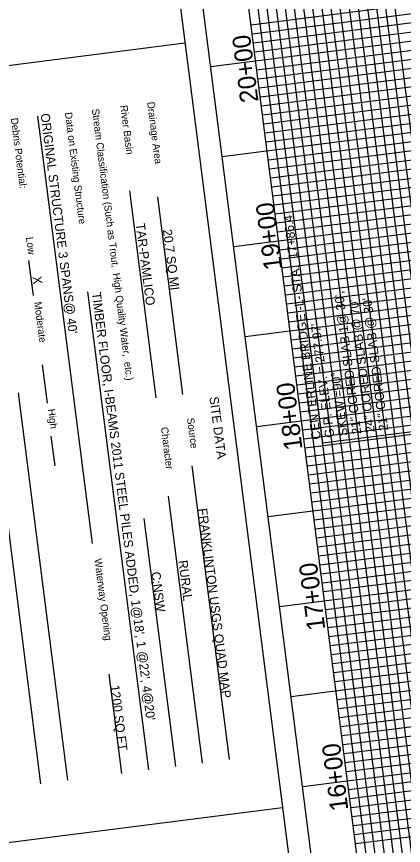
# Model space of a CAD drawing. Extents: x 2166991 to 2168450, y 842134 to 844444.
# Drawn here: x 2167499 to 2167712.5, y 843150.2 to 843607.1 of the extents above; entities that cross this region are included whole.
import ezdxf

# ---------------------------------------------------------------- set-up
doc = ezdxf.new("R2010")
doc.units = 0
for name, color, linetype in [('Exist Hydrographic Top of Bank', 7, 'Continuous'), ('Exist Plan Preparation Drainage Notes Label', 7, 'Continuous'), ('Prop Erosion Embankment Toe Protection Label', 7, 'Continuous'), ('Prop Erosion Embankment Toe Protection with Rip Rap 3 Detail CELL', 7, 'Continuous')]:
    doc.layers.add(name, color=color, linetype=linetype)

msp = doc.modelspace()

# ---------------------------------------------------------------- linework, layer by layer
at = {"layer": 'Exist Hydrographic Top of Bank'}
for p, q in [((2167668.02, 843371.86), (2167649.73, 843515.1)), ((2167765.56, 843384.32), (2167668.02, 843371.86))]:
    msp.add_line(p, q, dxfattribs=at)
at = {"layer": 'Exist Plan Preparation Drainage Notes Label'}
for p, q in [((2167538.09, 844014.21), (2167699.63, 842749.49)), ((2167538.09, 844014.21), (2167699.63, 842749.49)), ((2167785.16, 842770.49), (2167626.78, 844010.42)), ((2167710.76, 842760.99), (2167552.39, 844000.92)), ((2167735.56, 842764.16), (2167577.19, 844004.08)), ((2167796.87, 842797.19), (2167644.83, 843987.52)), ((2167801.83, 842797.82), (2167649.79, 843988.15)), ((2167806.79, 842798.46), (2167654.75, 843988.79)), ((2167811.75, 842799.09), (2167659.71, 843989.42)), ((2167757.19, 842792.12), (2167605.15, 843982.45)), ((2167762.15, 842792.76), (2167610.11, 843983.09)), ((2167767.11, 842793.39), (2167615.07, 843983.72)), ((2167772.07, 842794.02), (2167620.03, 843984.35)), ((2167777.03, 842794.66), (2167624.99, 843984.99)), ((2167786.95, 842795.92), (2167634.91, 843986.25)), ((2167791.91, 842796.56), (2167639.87, 843986.89)), ((2167737.35, 842789.59), (2167585.31, 843979.92)), ((2167742.31, 842790.22), (2167590.27, 843980.55)), ((2167747.27, 842790.86), (2167595.23, 843981.18)), ((2167752.23, 842791.49), (2167600.19, 843981.82)), ((2168124.47, 843665.7), (2167628.5, 843602.35)), ((2168125.1, 843660.74), (2167629.13, 843597.39)), ((2168125.74, 843655.78), (2167629.77, 843592.43)), ((2168126.37, 843650.82), (2167630.4, 843587.47)), ((2168127.01, 843645.86), (2167606.24, 843579.34)), ((2168127.64, 843640.9), (2167631.67, 843577.55)), ((2168128.27, 843635.94), (2167632.3, 843572.59)), ((2168128.91, 843630.98), (2167632.94, 843567.63)), ((2168129.54, 843626.02), (2167633.57, 843562.67)), ((2168130.17, 843621.06), (2167634.2, 843557.71)), ((2168130.81, 843616.1), (2167634.84, 843552.75)), ((2168131.44, 843611.14), (2167635.47, 843547.79)), ((2168132.07, 843606.18), (2167636.1, 843542.83)), ((2168132.71, 843601.22), (2167636.74, 843537.87)), ((2168133.34, 843596.26), (2167612.57, 843529.74)), ((2167046.37, 843522.95), (2167591.94, 843592.64)), ((2168133.97, 843591.3), (2167638, 843527.95)), ((2168134.61, 843586.34), (2167638.64, 843522.99)), ((2168135.24, 843581.38), (2167639.27, 843518.03)), ((2168135.87, 843576.42), (2167639.9, 843513.07)), ((2168136.51, 843571.46), (2167640.54, 843508.11)), ((2168137.14, 843566.5), (2167641.17, 843503.15)), ((2168137.77, 843561.54), (2167641.8, 843498.19)), ((2168138.41, 843556.58), (2167642.44, 843493.23)), ((2167540.89, 843316.64), (2167510.79, 843552.29)), ((2168139.04, 843551.62), (2167643.07, 843488.27)), ((2167512.44, 843184.21), (2167466.16, 843546.59)), ((2168139.68, 843546.66), (2167618.91, 843480.15)), ((2168140.31, 843541.7), (2167644.34, 843478.35)), ((2168140.94, 843536.74), (2167644.97, 843473.39)), ((2168141.58, 843531.78), (2167645.61, 843468.43)), ((2168142.21, 843526.83), (2167646.24, 843463.47)), ((2168142.84, 843521.87), (2167646.87, 843458.52)), ((2168143.48, 843516.91), (2167647.51, 843453.56)), ((2168144.11, 843511.95), (2167648.14, 843448.6)), ((2167576.04, 843396.95), (2167561.47, 843511.05)), ((2167590.88, 843398.85), (2167576.97, 843507.77)), ((2168144.74, 843506.99), (2167648.77, 843443.64)), ((2168145.38, 843502.03), (2167649.41, 843438.68)), ((2168146.01, 843497.07), (2167625.24, 843430.55)), ((2168146.64, 843492.11), (2167650.67, 843428.76)), ((2168147.28, 843487.15), (2167651.31, 843423.8)), ((2168147.91, 843482.19), (2167651.94, 843418.84)), ((2168148.54, 843477.23), (2167652.57, 843413.88)), ((2167508.31, 843453.37), (2167505.85, 843472.59)), ((2168149.18, 843472.27), (2167653.21, 843408.92)), ((2168149.81, 843467.31), (2167653.84, 843403.96)), ((2168150.44, 843462.35), (2167654.47, 843399)), ((2168151.08, 843457.39), (2167655.11, 843394.04)), ((2167571.96, 843191.81), (2167538.29, 843455.42)), ((2168151.71, 843452.43), (2167655.74, 843389.08)), ((2168152.35, 843447.47), (2167631.58, 843380.95)), ((2168152.98, 843442.51), (2167657.01, 843379.16)), ((2168153.61, 843437.55), (2167657.64, 843374.2)), ((2168154.25, 843432.59), (2167658.28, 843369.24)), ((2168154.88, 843427.63), (2167658.91, 843364.28)), ((2168155.51, 843422.67), (2167659.54, 843359.32)), ((2168156.15, 843417.71), (2167660.18, 843354.36)), ((2167513.19, 843415.17), (2167515.89, 843393.99)), ((2168156.78, 843412.75), (2167660.81, 843349.4)), ((2168157.41, 843407.79), (2167661.44, 843344.44)), ((2168158.05, 843402.83), (2167662.08, 843339.48)), ((2167527.32, 843186.11), (2167500.04, 843399.72)), ((2168158.68, 843397.87), (2167637.91, 843331.35)), ((2168159.31, 843392.91), (2167663.34, 843329.56)), ((2168159.95, 843387.95), (2167663.98, 843324.6)), ((2168160.58, 843382.99), (2167664.61, 843319.64)), ((2167520.3, 843359.51), (2167518.21, 843375.87)), ((2168161.21, 843378.03), (2167665.24, 843314.68)), ((2168161.85, 843373.07), (2167665.88, 843309.72)), ((2168162.48, 843368.11), (2167666.51, 843304.76)), ((2168163.11, 843363.15), (2167667.14, 843299.8)), ((2167616.62, 843197.52), (2167595.94, 843359.41)), ((2168163.75, 843358.2), (2167667.78, 843294.84)), ((2168164.38, 843353.24), (2167668.41, 843289.89)), ((2168165.02, 843348.28), (2167644.25, 843281.76)), ((2168165.65, 843343.32), (2167669.68, 843279.97)), ((2167601.72, 843195.61), (2167582.94, 843342.63)), ((2168166.28, 843338.36), (2167670.31, 843275.01)), ((2167586.84, 843193.71), (2167569.37, 843330.49)), ((2168166.92, 843333.4), (2167670.95, 843270.05)), ((2168167.55, 843328.44), (2167671.58, 843265.09)), ((2168168.18, 843323.48), (2167672.21, 843260.13)), ((2168168.82, 843318.52), (2167672.85, 843255.17)), ((2168169.45, 843313.56), (2167673.48, 843250.21)), ((2168170.08, 843308.6), (2167674.11, 843245.25)), ((2168170.72, 843303.64), (2167674.75, 843240.29)), ((2168171.35, 843298.68), (2167650.58, 843232.16)), ((2168171.98, 843293.72), (2167676.01, 843230.37)), ((2168172.62, 843288.76), (2167676.65, 843225.41)), ((2168173.25, 843283.8), (2167677.28, 843220.45)), ((2168173.88, 843278.84), (2167677.91, 843215.49)), ((2168174.52, 843273.88), (2167678.55, 843210.53)), ((2168175.15, 843268.92), (2167679.18, 843205.57)), ((2168175.78, 843263.96), (2167679.81, 843200.61)), ((2168176.42, 843259), (2167680.45, 843195.65)), ((2168177.05, 843254.04), (2167681.08, 843190.69)), ((2168177.69, 843249.08), (2167656.92, 843182.56)), ((2167557.08, 843189.91), (2167550.1, 843244.57)), ((2168178.32, 843244.12), (2167682.35, 843180.77)), ((2168178.95, 843239.16), (2167682.98, 843175.81)), ((2168179.59, 843234.2), (2167683.62, 843170.85)), ((2168180.22, 843229.24), (2167684.25, 843165.89)), ((2168180.85, 843224.28), (2167684.88, 843160.93)), ((2168181.49, 843219.32), (2167685.52, 843155.97)), ((2168182.12, 843214.36), (2167686.15, 843151.01)), ((2167100.22, 843101.38), (2167645.78, 843171.06))]:
    msp.add_line(p, q, dxfattribs=at)

# ---------------------------------------------------------------- texts
at = {"layer": 'Exist Hydrographic Top of Bank'}
for s, p in [('CENTERLINE BRIDGE -L- STA.  17+86.4', (2167666.96, 843374.29)), ('21" CORED SLAB 1@ 30\',', (2167689.28, 843377.14)), ('24" CORED SLAB @ 70\'', (2167696.72, 843378.09)), ('21" CORED SLAB @ 30\'', (2167704.16, 843379.04)), ("G.P. ELEV. = 277.97'", (2167674.4, 843375.24)), ('SKEW =90%%d', (2167681.84, 843376.19))]:
    msp.add_text(s, height=5, rotation=97.279, dxfattribs=at).set_placement(p)
at = {"layer": 'Exist Plan Preparation Drainage Notes Label'}
for s, height, p in [('River Basin', 4, (2167556.24, 843557.98)), ('Drainage Area', 4, (2167571.08, 843559.89)), ('Data on Existing Structure', 4, (2167525.67, 843554.13)), ('Stream Classification (Such as Trout,  High Quality Water,  etc.)', 4, (2167540.57, 843556.06)), ('Debris Potential:', 4, (2167495.83, 843551.05)), ('Low', 4, (2167504.22, 843485.35)), ('Moderate', 4, (2167508.78, 843449.66)), ('SITE DATA', 5, (2167605.44, 843397.29)), ('High', 4, (2167516.32, 843390.6)), ('Source', 4, (2167593.08, 843385.65)), ('Character', 4, (2167578.66, 843380.58)), ('Waterway Opening', 4, (2167542.03, 843308.06))]:
    msp.add_text(s, height=height, rotation=277.279, dxfattribs=at).set_placement(p)
at = {"layer": 'Prop Erosion Embankment Toe Protection Label'}
for s, p in [('20+00', (2167632.57, 843560.33)), ('19+00', (2167645.6, 843467.97)), ('18+00', (2167656.87, 843368.68)), ('17+00', (2167669.45, 843269.34)), ('16+00', (2167682.16, 843169.8))]:
    msp.add_text(s, height=10, rotation=97.279, dxfattribs=at).set_placement(p)
at = {"layer": 'Prop Erosion Embankment Toe Protection with Rip Rap 3 Detail CELL'}
for s, p in [("ORIGINAL STRUCTURE 3 SPANS@ 40'", (2167512.28, 843553.45)), ('TAR-PAMLICO', (2167564.8, 843492.89)), ('20.7 SQ MI', (2167579.78, 843489.52)), ('X', (2167507.79, 843463.69)), ("TIMBER FLOOR, I-BEAMS 2011 STEEL PILES ADDED, 1@18', 1 @22', 4@20' ", (2167540.56, 843454.79)), ('FRANKLINTON USGS QUAD MAP', (2167599.16, 843335.72)), ('RURAL', (2167588.33, 843307.09)), ('C;NSW', (2167573.33, 843300.73)), ('1200 SQ FT', (2167550.76, 843238.25))]:
    msp.add_text(s, height=5, rotation=277.279, dxfattribs=at).set_placement(p)

doc.saveas('drawing.dxf')
